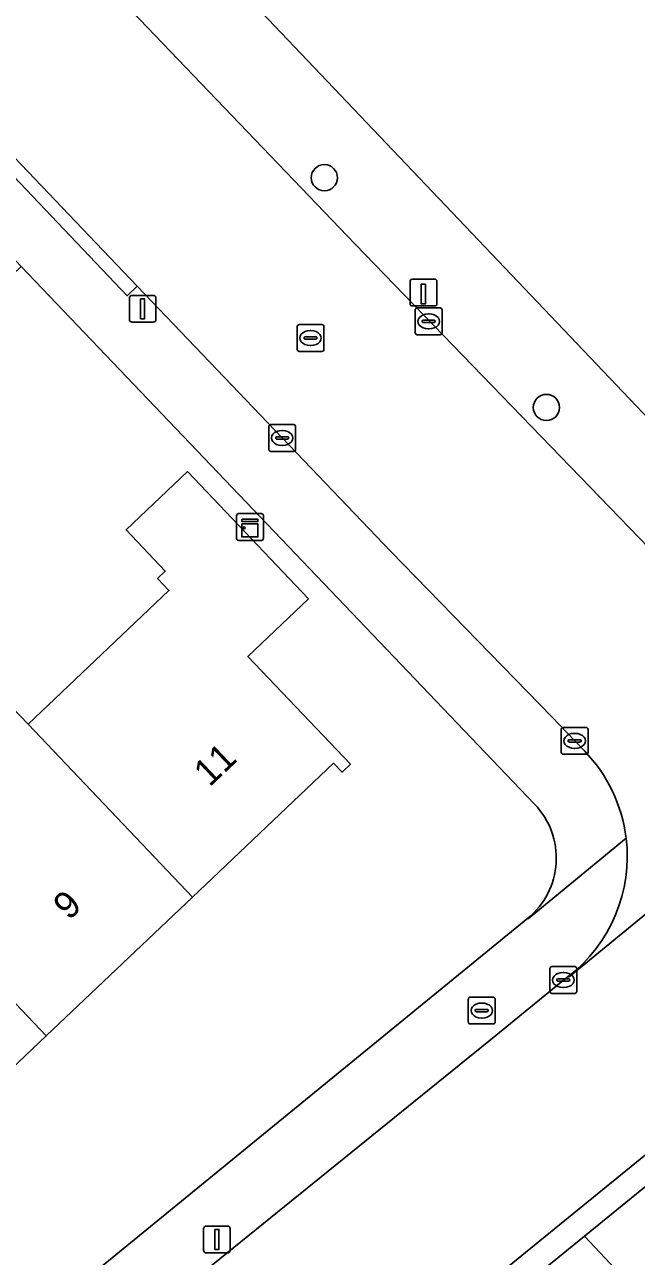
# Model space of a CAD drawing. Extents: x 159352 to 160617, y 385888 to 387323.
# Drawn here: x 160063.91 to 160086.72, y 386373.72 to 386419.67 of the extents above; entities that cross this region are included whole.
import ezdxf

# ---------------------------------------------------------------- set-up
doc = ezdxf.new("R2010")
doc.units = 0
for name, color, linetype in [('IMGEO_Boom', 7, 'Continuous'), ('IMGEO_Brandkraan', 7, 'Continuous'), ('IMGEO_Erf', 7, 'Continuous'), ('IMGEO_Groenvoorziening', 7, 'Continuous'), ('IMGEO_Kast', 7, 'Continuous'), ('IMGEO_Kolk', 7, 'Continuous'), ('IMGEO_Laadpaal', 7, 'Continuous'), ('IMGEO_Lichtmast', 7, 'Continuous'), ('IMGEO_Pand', 7, 'Continuous'), ('IMGEO_Pand_nummerreeks', 7, 'Continuous'), ('IMGEO_Rijbaan_lokaal_open', 7, 'Continuous'), ('IMGEO_Rioolput', 7, 'Continuous'), ('IMGEO_Voetpad_open', 7, 'Continuous')]:
    doc.layers.add(name, color=color, linetype=linetype)

msp = doc.modelspace()

# ---------------------------------------------------------------- linework, layer by layer
at = {"layer": 'IMGEO_Boom'}
for centre in [(160075.091, 386413.958), (160083.371, 386405.389)]:
    msp.add_circle(centre, 0.489, dxfattribs=at)
at = {"layer": 'IMGEO_Brandkraan'}
for p, q in [((160080.459, 386382.467), (160080.459, 386383.319)), ((160080.534, 386383.393), (160081.386, 386383.393)), ((160081.46, 386383.319), (160081.46, 386382.467)), ((160080.718, 386382.887), (160080.718, 386382.899)), ((160081.156, 386382.85), (160080.758, 386382.85)), ((160080.761, 386382.936), (160081.159, 386382.936)), ((160080.947, 386383.173), (160080.972, 386383.173)), ((160081.202, 386382.899), (160081.202, 386382.887)), ((160081.386, 386382.393), (160080.534, 386382.393)), ((160080.97, 386382.613), (160080.945, 386382.613))]:
    msp.add_line(p, q, dxfattribs=at)
for points in [[(160080.459, 386382.467), (160080.459, 386383.319)], [(160080.534, 386383.393), (160081.386, 386383.393)], [(160081.46, 386383.319), (160081.46, 386382.467)], [(160081.386, 386382.393), (160080.534, 386382.393)]]:
    msp.add_lwpolyline(points, dxfattribs=at)
for centre, radius, start, end in [((160080.536, 386383.317), 0.0765, 91.552, 178.448), ((160080.536, 386383.317), 0.0765, 91.552, 178.448), ((160081.384, 386383.317), 0.0765, 1.552, 88.448), ((160081.384, 386383.317), 0.0765, 1.552, 88.448), ((160080.758, 386382.896), 0.0403, 85.8775, 175.7526), ((160080.755, 386382.886), 0.0366, 178.938, 274.7102), ((160081.159, 386382.893), 0.043, 264.8664, 352.4533), ((160081.163, 386382.898), 0.0386, 1.7309, 96.639), ((160080.536, 386382.469), 0.0765, 181.552, 268.448), ((160080.536, 386382.469), 0.0765, 181.552, 268.448), ((160081.384, 386382.469), 0.0765, 271.552, 358.448), ((160081.384, 386382.469), 0.0765, 271.552, 358.448)]:
    msp.add_arc(centre, radius, start, end, dxfattribs=at)
for centre, major_axis, ratio, start_param, end_param in [((160080.946, 386382.893), (-0.387, 0.002), 0.722429, 4.712389, 7.853982), ((160080.971, 386382.893), (-0.39, 0.002), 0.717154, 1.570796, 4.712389)]:
    msp.add_ellipse(centre, major_axis=major_axis, ratio=ratio, start_param=start_param, end_param=end_param, dxfattribs=at)
at = {"layer": 'IMGEO_Erf'}
for points in [[(160067.602, 386425.553), (160093.335, 386398.496)], [(160082.931, 386390.588), (160063.784, 386410.644), (160060.927, 386407.917), (160063.335, 386405.379), (160057.813, 386400.141), (160055.952, 386398.376), (160053.544, 386400.915), (160050, 386397.615), (160052.555, 386394.93), (160050.478, 386392.953), (160047.923, 386395.638), (160044.456, 386392.348), (160047.011, 386389.663), (160044.933, 386387.686), (160042.378, 386390.371), (160039.019, 386387.184), (160041.574, 386384.499), (160039.496, 386382.522), (160036.941, 386385.207), (160033.746, 386381.896), (160036.266, 386379.163), (160030.73, 386374.058)], [(160042.224, 386372.853), (160047.679, 386378.035), (160053.135, 386383.217), (160058.59, 386388.399), (160061.462, 386391.127), (160059.989, 386392.727), (160062.534, 386395.143), (160064.045, 386393.581), (160069.294, 386398.567), (160068.873, 386399.011), (160069.16, 386399.284), (160067.699, 386400.822), (160069.987, 386402.995), (160074.498, 386398.246), (160072.24, 386396.101), (160076.062, 386392.078), (160075.749, 386391.78), (160075.428, 386392.118), (160070.175, 386387.128), (160064.72, 386381.946), (160059.265, 386376.764), (160053.81, 386371.583)], [(160139.92, 386394.943), (160130.732, 386398.999), (160130.393, 386399.14), (160114.995, 386386.46), (160108.815, 386394.053), (160084.79, 386374.482), (160100.414, 386357.83), (160121.621, 386335.228), (160131.394, 386324.811), (160143.378, 386312.039), (160220.755, 386365.169), (160205.701, 386386.38), (160199.403, 386380.85), (160179.637, 386363.491), (160178.327, 386364.971), (160163.291, 386351.691), (160159.97, 386352.841), (160148.703, 386342.922), (160127.044, 386367.689), (160141.856, 386380.854)], [(160044.803, 386355.392), (160082.673, 386386.333)]]:
    msp.add_lwpolyline(points, dxfattribs=at)
msp.add_arc((160080.837, 386388.58), 2.902, 309.2614, 43.7989, dxfattribs=at)
at = {"layer": 'IMGEO_Groenvoorziening'}
msp.add_lwpolyline([(160100.414, 386357.83), (160084.79, 386374.482), (160080.098, 386370.657), (160089.781, 386357.507), (160090.472, 386356.824), (160091.29, 386356.3), (160092.199, 386355.957), (160092.858, 386355.835), (160097.183, 386354.798)], close=True, dxfattribs=at)
at = {"layer": 'IMGEO_Kast'}
for p, q in [((160071.817, 386400.506), (160071.817, 386401.347)), ((160071.817, 386401.347), (160071.817, 386400.506)), ((160071.892, 386401.431), (160072.733, 386401.431)), ((160072.733, 386401.431), (160071.892, 386401.431)), ((160072.817, 386401.356), (160072.817, 386400.515)), ((160072.817, 386400.515), (160072.817, 386401.356)), ((160072.742, 386400.431), (160071.901, 386400.431)), ((160071.901, 386400.431), (160072.742, 386400.431))]:
    msp.add_line(p, q, dxfattribs=at)
for points in [[(160072.012, 386401.221), (160072.612, 386401.221), (160072.612, 386401.136), (160072.012, 386401.136), (160072.012, 386401.221)], [(160072.012, 386401.046), (160072.612, 386401.046), (160072.612, 386400.557), (160072.012, 386400.557), (160072.012, 386401.046)]]:
    msp.add_lwpolyline(points, dxfattribs=at)
msp.add_circle((160072.096, 386400.895), 0.0377, dxfattribs=at)
for centre, start, end in [((160071.895, 386401.353), 92.4484, 184.2845), ((160071.895, 386401.353), 92.4484, 184.2845), ((160072.739, 386401.353), 2.4484, 94.2845), ((160072.739, 386401.353), 2.4484, 94.2845), ((160071.895, 386400.509), 182.4484, 274.2845), ((160071.895, 386400.509), 182.4484, 274.2845), ((160072.739, 386400.509), 272.4484, 4.2845), ((160072.739, 386400.509), 272.4484, 4.2845)]:
    msp.add_arc(centre, 0.0779, start, end, dxfattribs=at)
at = {"layer": 'IMGEO_Kolk'}
for p, q in [((160078.48, 386408.174), (160078.48, 386409.026)), ((160078.555, 386409.1), (160079.407, 386409.1)), ((160079.481, 386409.026), (160079.481, 386408.174)), ((160078.739, 386408.594), (160078.739, 386408.606)), ((160079.177, 386408.557), (160078.779, 386408.557)), ((160078.782, 386408.643), (160079.18, 386408.643)), ((160078.968, 386408.88), (160078.993, 386408.88)), ((160079.223, 386408.606), (160079.223, 386408.594)), ((160079.407, 386408.1), (160078.555, 386408.1)), ((160078.991, 386408.32), (160078.966, 386408.32)), ((160073.019, 386403.825), (160073.019, 386404.677)), ((160073.094, 386404.751), (160073.946, 386404.751)), ((160073.507, 386404.531), (160073.532, 386404.531)), ((160074.02, 386404.677), (160074.02, 386403.825)), ((160073.278, 386404.245), (160073.278, 386404.257)), ((160073.716, 386404.208), (160073.318, 386404.208)), ((160073.321, 386404.294), (160073.719, 386404.294)), ((160073.53, 386403.971), (160073.505, 386403.971)), ((160073.762, 386404.257), (160073.762, 386404.245)), ((160073.946, 386403.751), (160073.094, 386403.751)), ((160083.924, 386392.527), (160083.924, 386393.379)), ((160083.999, 386393.453), (160084.851, 386393.453)), ((160084.925, 386393.379), (160084.925, 386392.527)), ((160084.183, 386392.947), (160084.183, 386392.959)), ((160084.621, 386392.91), (160084.223, 386392.91)), ((160084.226, 386392.996), (160084.624, 386392.996)), ((160084.412, 386393.233), (160084.437, 386393.233)), ((160084.667, 386392.959), (160084.667, 386392.947)), ((160084.851, 386392.453), (160083.999, 386392.453)), ((160084.435, 386392.673), (160084.41, 386392.673)), ((160083.502, 386383.606), (160083.502, 386384.458)), ((160083.577, 386384.532), (160084.429, 386384.532)), ((160083.99, 386384.312), (160084.015, 386384.312)), ((160084.503, 386384.458), (160084.503, 386383.606)), ((160083.761, 386384.026), (160083.761, 386384.038)), ((160084.199, 386383.989), (160083.801, 386383.989)), ((160083.804, 386384.075), (160084.202, 386384.075)), ((160084.013, 386383.752), (160083.988, 386383.752)), ((160084.245, 386384.038), (160084.245, 386384.026)), ((160084.429, 386383.532), (160083.577, 386383.532))]:
    msp.add_line(p, q, dxfattribs=at)
for points in [[(160078.48, 386408.174), (160078.48, 386409.026)], [(160078.555, 386409.1), (160079.407, 386409.1)], [(160079.481, 386409.026), (160079.481, 386408.174)], [(160079.407, 386408.1), (160078.555, 386408.1)], [(160073.019, 386403.825), (160073.019, 386404.677)], [(160073.094, 386404.751), (160073.946, 386404.751)], [(160074.02, 386404.677), (160074.02, 386403.825)], [(160073.946, 386403.751), (160073.094, 386403.751)], [(160083.924, 386392.527), (160083.924, 386393.379)], [(160083.999, 386393.453), (160084.851, 386393.453)], [(160084.925, 386393.379), (160084.925, 386392.527)], [(160084.851, 386392.453), (160083.999, 386392.453)], [(160083.502, 386383.606), (160083.502, 386384.458)], [(160083.577, 386384.532), (160084.429, 386384.532)], [(160084.503, 386384.458), (160084.503, 386383.606)], [(160084.429, 386383.532), (160083.577, 386383.532)]]:
    msp.add_lwpolyline(points, dxfattribs=at)
for centre, radius, start, end in [((160078.557, 386409.024), 0.0765, 91.552, 178.448), ((160078.557, 386409.024), 0.0765, 91.552, 178.448), ((160079.405, 386409.024), 0.0765, 1.552, 88.448), ((160079.405, 386409.024), 0.0765, 1.552, 88.448), ((160078.779, 386408.603), 0.0403, 85.8775, 175.7526), ((160078.776, 386408.593), 0.0366, 178.938, 274.7102), ((160079.18, 386408.6), 0.043, 264.8664, 352.4533), ((160079.184, 386408.605), 0.0386, 1.7309, 96.639), ((160078.557, 386408.176), 0.0765, 181.552, 268.448), ((160078.557, 386408.176), 0.0765, 181.552, 268.448), ((160079.405, 386408.176), 0.0765, 271.552, 358.448), ((160079.405, 386408.176), 0.0765, 271.552, 358.448), ((160073.096, 386404.675), 0.0765, 91.552, 178.448), ((160073.096, 386404.675), 0.0765, 91.552, 178.448), ((160073.944, 386404.675), 0.0765, 1.552, 88.448), ((160073.944, 386404.675), 0.0765, 1.552, 88.448), ((160073.318, 386404.254), 0.0403, 85.8775, 175.7526), ((160073.315, 386404.244), 0.0366, 178.938, 274.7102), ((160073.719, 386404.251), 0.043, 264.8664, 352.4533), ((160073.723, 386404.256), 0.0386, 1.7309, 96.639), ((160073.096, 386403.827), 0.0765, 181.552, 268.448), ((160073.096, 386403.827), 0.0765, 181.552, 268.448), ((160073.944, 386403.827), 0.0765, 271.552, 358.448), ((160073.944, 386403.827), 0.0765, 271.552, 358.448), ((160084.001, 386393.377), 0.0765, 91.552, 178.448), ((160084.001, 386393.377), 0.0765, 91.552, 178.448), ((160084.849, 386393.377), 0.0765, 1.552, 88.448), ((160084.849, 386393.377), 0.0765, 1.552, 88.448), ((160084.223, 386392.956), 0.0403, 85.8775, 175.7526), ((160084.22, 386392.946), 0.0366, 178.938, 274.7102), ((160084.624, 386392.953), 0.043, 264.8664, 352.4533), ((160084.628, 386392.958), 0.0386, 1.7309, 96.639), ((160084.001, 386392.529), 0.0765, 181.552, 268.448), ((160084.001, 386392.529), 0.0765, 181.552, 268.448), ((160084.849, 386392.529), 0.0765, 271.552, 358.448), ((160084.849, 386392.529), 0.0765, 271.552, 358.448), ((160083.579, 386384.456), 0.0765, 91.552, 178.448), ((160083.579, 386384.456), 0.0765, 91.552, 178.448), ((160084.427, 386384.456), 0.0765, 1.552, 88.448), ((160084.427, 386384.456), 0.0765, 1.552, 88.448), ((160083.801, 386384.035), 0.0403, 85.8775, 175.7526), ((160083.798, 386384.025), 0.0366, 178.938, 274.7102), ((160084.202, 386384.032), 0.043, 264.8664, 352.4533), ((160084.206, 386384.037), 0.0386, 1.7309, 96.639), ((160083.579, 386383.608), 0.0765, 181.552, 268.448), ((160083.579, 386383.608), 0.0765, 181.552, 268.448), ((160084.427, 386383.608), 0.0765, 271.552, 358.448), ((160084.427, 386383.608), 0.0765, 271.552, 358.448)]:
    msp.add_arc(centre, radius, start, end, dxfattribs=at)
for centre, major_axis, ratio, start_param, end_param in [((160078.967, 386408.6), (-0.387, 0.002), 0.722429, 4.712389, 7.853982), ((160078.992, 386408.6), (-0.39, 0.002), 0.717154, 1.570796, 4.712389), ((160073.506, 386404.251), (-0.387, 0.002), 0.722429, 4.712389, 7.853982), ((160073.531, 386404.251), (-0.39, 0.002), 0.717154, 1.570796, 4.712389), ((160084.411, 386392.953), (-0.387, 0.002), 0.722429, 4.712389, 7.853982), ((160084.436, 386392.953), (-0.39, 0.002), 0.717154, 1.570796, 4.712389), ((160083.989, 386384.032), (-0.387, 0.002), 0.722429, 4.712389, 7.853982), ((160084.014, 386384.032), (-0.39, 0.002), 0.717154, 1.570796, 4.712389)]:
    msp.add_ellipse(centre, major_axis=major_axis, ratio=ratio, start_param=start_param, end_param=end_param, dxfattribs=at)
at = {"layer": 'IMGEO_Laadpaal'}
for p, q in [((160078.287, 386410.09), (160078.287, 386409.249)), ((160078.287, 386410.09), (160078.287, 386409.249)), ((160079.203, 386410.174), (160078.362, 386410.174)), ((160079.203, 386410.174), (160078.362, 386410.174)), ((160079.287, 386409.258), (160079.287, 386410.099)), ((160079.287, 386409.258), (160079.287, 386410.099)), ((160078.371, 386409.174), (160079.212, 386409.174)), ((160078.371, 386409.174), (160079.212, 386409.174))]:
    msp.add_line(p, q, dxfattribs=at)
msp.add_lwpolyline([(160078.702, 386409.987), (160078.862, 386409.987), (160078.862, 386409.254), (160078.702, 386409.254), (160078.702, 386409.987)], dxfattribs=at)
for centre, start, end in [((160078.365, 386410.096), 92.4484, 184.2845), ((160078.365, 386410.096), 92.4484, 184.2845), ((160079.209, 386410.096), 2.4484, 94.2845), ((160079.209, 386410.096), 2.4484, 94.2845), ((160078.365, 386409.252), 182.4484, 274.2845), ((160078.365, 386409.252), 182.4484, 274.2845), ((160079.209, 386409.252), 272.4484, 4.2845), ((160079.209, 386409.252), 272.4484, 4.2845)]:
    msp.add_arc(centre, 0.0779, start, end, dxfattribs=at)
at = {"layer": 'IMGEO_Lichtmast'}
for p, q in [((160067.82, 386408.671), (160067.82, 386409.471)), ((160067.82, 386409.471), (160067.82, 386408.671)), ((160067.92, 386409.571), (160068.71, 386409.571)), ((160068.71, 386409.571), (160067.92, 386409.571)), ((160068.81, 386409.471), (160068.81, 386408.671)), ((160068.81, 386408.671), (160068.81, 386409.471)), ((160068.71, 386408.571), (160067.92, 386408.571)), ((160067.92, 386408.571), (160068.71, 386408.571)), ((160070.588, 386373.953), (160070.588, 386374.753)), ((160070.588, 386374.753), (160070.588, 386373.953)), ((160070.688, 386374.853), (160071.478, 386374.853)), ((160071.478, 386374.853), (160070.688, 386374.853)), ((160071.578, 386374.753), (160071.578, 386373.953)), ((160071.578, 386373.953), (160071.578, 386374.753)), ((160071.478, 386373.853), (160070.688, 386373.853)), ((160070.688, 386373.853), (160071.478, 386373.853))]:
    msp.add_line(p, q, dxfattribs=at)
for points in [[(160068.24, 386409.446), (160068.39, 386409.446), (160068.39, 386408.696), (160068.24, 386408.696), (160068.24, 386409.446)], [(160071.008, 386374.728), (160071.158, 386374.728), (160071.158, 386373.978), (160071.008, 386373.978), (160071.008, 386374.728)]]:
    msp.add_lwpolyline(points, dxfattribs=at)
for centre, start, end in [((160067.92, 386409.471), 90, 180), ((160067.92, 386409.471), 90, 180), ((160068.71, 386409.471), 0, 90), ((160068.71, 386409.471), 360, 90), ((160067.92, 386408.671), 180, 270), ((160067.92, 386408.671), 180, 270), ((160068.71, 386408.671), 270, 0), ((160068.71, 386408.671), 270, 0), ((160070.688, 386374.753), 90, 180), ((160070.688, 386374.753), 90, 180), ((160071.478, 386374.753), 0, 90), ((160071.478, 386374.753), 360, 90), ((160070.688, 386373.953), 180, 270), ((160070.688, 386373.953), 180, 270), ((160071.478, 386373.953), 270, 0), ((160071.478, 386373.953), 270, 0)]:
    msp.add_arc(centre, 0.1, start, end, dxfattribs=at)
at = {"layer": 'IMGEO_Pand'}
for points in [[(160070.175, 386387.128), (160075.428, 386392.118), (160075.749, 386391.78), (160076.062, 386392.078), (160072.24, 386396.101), (160074.498, 386398.246), (160069.987, 386402.995), (160067.699, 386400.822), (160069.16, 386399.284), (160068.873, 386399.011), (160069.294, 386398.567), (160064.045, 386393.581)], [(160064.045, 386393.581), (160062.534, 386395.143), (160059.989, 386392.727), (160061.462, 386391.127), (160058.59, 386388.399), (160064.72, 386381.946), (160070.175, 386387.128)], [(160058.59, 386388.399), (160053.135, 386383.217), (160059.265, 386376.764), (160064.72, 386381.946)]]:
    msp.add_lwpolyline(points, close=True, dxfattribs=at)
at = {"layer": 'IMGEO_Rijbaan_lokaal_open'}
for points in [[(160053.676, 386435.154), (160040.522, 386448.973), (160035.066, 386454.705), (160034.378, 386455.424), (160009.601, 386481.243), (160007.388, 386483.587), (160002.328, 386478.752), (160002.196, 386478.595), (160008.562, 386472.269), (160023.271, 386456.824), (160044.724, 386434.375), (160061.731, 386416.584), (160068.108, 386409.914), (160077.575, 386400.01), (160083.59, 386393.835), (160084.427, 386392.954), (160084.785, 386392.581)], [(160090.602, 386396.625), (160090.289, 386396.916), (160088.285, 386399.017), (160076.236, 386411.478), (160065.327, 386422.882), (160065.32, 386422.878), (160053.677, 386435.138), (160053.676, 386435.154)], [(160107.004, 386402.696), (160104.84, 386400.971), (160099.002, 386396.272), (160084.224, 386384.153), (160084.187, 386384.163), (160084.004, 386384.031), (160081.488, 386381.964), (160066.832, 386370.103), (160049.13, 386355.617), (160053.578, 386350.182), (160059.668, 386355.151), (160079.001, 386371.136), (160081.386, 386372.884), (160100.634, 386388.561), (160103.571, 386390.952), (160110.155, 386396.315)], [(160084.187, 386384.163), (160084.224, 386384.153), (160099.002, 386396.272)]]:
    msp.add_lwpolyline(points, dxfattribs=at)
for centre, radius, start, end in [((160080.723, 386388.635), 5.663, 6.9768, 44.1667), ((160080.727, 386388.64), 5.659, 307.6993, 6.9286)]:
    msp.add_arc(centre, radius, start, end, dxfattribs=at)
at = {"layer": 'IMGEO_Rioolput'}
for p, q in [((160074.075, 386407.552), (160074.075, 386408.404)), ((160074.15, 386408.478), (160075.002, 386408.478)), ((160074.563, 386408.258), (160074.588, 386408.258)), ((160075.076, 386408.404), (160075.076, 386407.552)), ((160074.334, 386407.972), (160074.334, 386407.984)), ((160074.772, 386407.935), (160074.374, 386407.935)), ((160074.377, 386408.021), (160074.775, 386408.021)), ((160074.586, 386407.698), (160074.561, 386407.698)), ((160074.818, 386407.984), (160074.818, 386407.972)), ((160075.002, 386407.478), (160074.15, 386407.478))]:
    msp.add_line(p, q, dxfattribs=at)
for points in [[(160074.075, 386407.552), (160074.075, 386408.404)], [(160074.15, 386408.478), (160075.002, 386408.478)], [(160075.076, 386408.404), (160075.076, 386407.552)], [(160075.002, 386407.478), (160074.15, 386407.478)]]:
    msp.add_lwpolyline(points, dxfattribs=at)
for centre, radius, start, end in [((160074.152, 386408.402), 0.0765, 91.552, 178.448), ((160074.152, 386408.402), 0.0765, 91.552, 178.448), ((160075, 386408.402), 0.0765, 1.552, 88.448), ((160075, 386408.402), 0.0765, 1.552, 88.448), ((160074.374, 386407.981), 0.0403, 85.8775, 175.7526), ((160074.371, 386407.971), 0.0366, 178.938, 274.7102), ((160074.775, 386407.978), 0.043, 264.8664, 352.4533), ((160074.779, 386407.983), 0.0386, 1.7309, 96.639), ((160074.152, 386407.554), 0.0765, 181.552, 268.448), ((160074.152, 386407.554), 0.0765, 181.552, 268.448), ((160075, 386407.554), 0.0765, 271.552, 358.448), ((160075, 386407.554), 0.0765, 271.552, 358.448)]:
    msp.add_arc(centre, radius, start, end, dxfattribs=at)
for centre, major_axis, ratio, start_param, end_param in [((160074.562, 386407.978), (-0.387, 0.002), 0.722429, 4.712389, 7.853982), ((160074.587, 386407.978), (-0.39, 0.002), 0.717154, 1.570796, 4.712389)]:
    msp.add_ellipse(centre, major_axis=major_axis, ratio=ratio, start_param=start_param, end_param=end_param, dxfattribs=at)
at = {"layer": 'IMGEO_Voetpad_open'}
for points in [[(160068.108, 386409.914), (160067.733, 386409.558), (160061.369, 386416.24), (160061.731, 386416.584), (160044.724, 386434.375), (160023.271, 386456.824), (160008.562, 386472.269), (160002.196, 386478.595)], [(160000, 386477.455), (160062.705, 386411.774), (160063.784, 386410.644), (160082.931, 386390.588)], [(160093.335, 386398.496), (160067.602, 386425.553)], [(160065.327, 386422.882), (160076.236, 386411.478), (160088.285, 386399.017), (160088.644, 386399.364), (160090.961, 386396.972), (160090.602, 386396.625)], [(160084.785, 386392.581), (160084.427, 386392.954), (160083.59, 386393.835), (160077.575, 386400.01), (160068.108, 386409.914)], [(160110.155, 386396.315), (160103.571, 386390.952), (160103.857, 386390.599), (160100.918, 386388.217), (160100.634, 386388.561), (160081.386, 386372.884), (160079.001, 386371.136), (160059.668, 386355.151), (160053.578, 386350.182), (160054.162, 386349.527), (160055.245, 386350.409), (160057.684, 386352.391), (160060.571, 386354.736), (160080.098, 386370.657), (160084.79, 386374.482), (160108.815, 386394.053), (160110.975, 386395.813)], [(160086.344, 386389.323), (160082.698, 386386.326), (160082.673, 386386.333), (160044.803, 386355.392), (160041.378, 386352.293)], [(160082.673, 386386.333), (160082.698, 386386.326), (160086.344, 386389.323)], [(160081.488, 386381.964), (160084.004, 386384.031), (160084.187, 386384.163)], [(160047.117, 386353.97), (160049.13, 386355.617), (160066.832, 386370.103), (160081.488, 386381.964)]]:
    msp.add_lwpolyline(points, dxfattribs=at)
msp.add_lwpolyline([(160068.108, 386409.914), (160061.731, 386416.584), (160061.369, 386416.24), (160067.733, 386409.558)], close=True, dxfattribs=at)
for centre, radius, start, end in [((160080.723, 386388.635), 5.663, 6.9768, 44.1667), ((160080.837, 386388.58), 2.902, 309.2614, 43.7989), ((160080.727, 386388.64), 5.659, 307.6993, 6.9286)]:
    msp.add_arc(centre, radius, start, end, dxfattribs=at)

# ---------------------------------------------------------------- texts
at = {"layer": 'IMGEO_Pand_nummerreeks'}
for s, rotation, p in [('11', 43.5283, (160070.809, 386391.207)), ('9', 43.5276, (160065.569, 386386.229))]:
    msp.add_text(s, height=1, rotation=rotation, dxfattribs=at).set_placement(p)

doc.saveas('drawing.dxf')
